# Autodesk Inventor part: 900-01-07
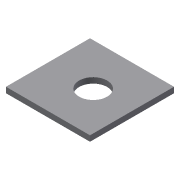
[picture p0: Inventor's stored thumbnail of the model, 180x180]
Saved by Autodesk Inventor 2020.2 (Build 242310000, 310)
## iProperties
Created: 2015-10
Part Number: 900-01-07
Material: Ogólny
Document SubType Name: Modeling
Designer: F.Stasiak
Density: 1 g/cm^3
Appearance: Domyślna
Catalog Web Link: www.expertbooks.pl
Manager: www.cadconsulting.pl
Company: Fabian Stasiak CAD Consulting
Author: F.Stasiak
Subject: Zbiór ćwiczeń. Autodesk Inventor 2020. Kurs Professional
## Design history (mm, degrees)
sketch "Szkic1"
  geometry: L1 (60, 60)-(-60, 60); L2 (-60, 60)-(-60, -60); L3 (-60, -60)-(60, -60); L4 (60, -60)-(60, 60); L5 (60, 60)-(-60, -60); L6 (-60, 60)-(60, -60); C1 r 20 at (4.5, 0); 2 further points
  constraints: 12 end point, 3 midpoint, 2 parallel, 1 centre point, 1 horizontal, 1 horizontal alignment, 1 perpendicular
  dimensions: "d0" = 120 distance of L3.end L2.end; "d1" = 120 distance of L2.end L1.end; "d5" = 40 diameter of C1; "d6" = 64.5 distance from line of C1.centre L2
extrude "Wyciągnięcie proste1" new body sketch "Szkic1" distance "d3" = 8; taper "d4" = 0 deg
node "Bryła1"
